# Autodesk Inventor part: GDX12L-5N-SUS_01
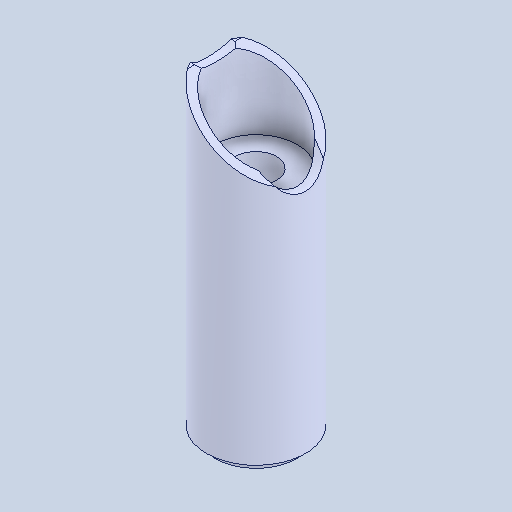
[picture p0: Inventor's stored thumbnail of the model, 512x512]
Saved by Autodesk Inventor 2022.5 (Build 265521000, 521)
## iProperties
Created: 2024-06
Part Number: GDX12L-5N-SUS_01
Material: 一般
Document SubType Name: Modeling
Designer: ImaoCorp
Density: 1 g/cm^3
Appearance: 既定
Author: ImaoCorp
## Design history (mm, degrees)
feature "GDX12L-5N-SUS_01"
node "ソリッド1"
